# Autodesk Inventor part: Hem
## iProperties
Shininess: 64.0
Length Units: 11269
Angle Units: 11279
Time Units: 11290
Mass Units: 11283
Length Display Precision: 3
Angle Display Precision: 2
Compacted: True
Part Number: Hem
Document SubType Name: Sheet Metal
Created: 2003-09
Material: Stainless Steel, 440C
Designer: Ronald Myers
Manufacturer: Standard
Standards Organization: Custom
Density: 1 g/cm^3
Sheet Metal Rule: 1.2 mm Stainless
Density: 0.0
Volumn: 0.0
Area: 0.0
PropertySet Name: Model Information
Control State: 0
Master: False
Checked Out: False
Author: Ronald Myers
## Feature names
1. Plate1
2. Bend1
3. Plate2
4. Bend2
5. Plate3
6. Bend3
7. Cut1
